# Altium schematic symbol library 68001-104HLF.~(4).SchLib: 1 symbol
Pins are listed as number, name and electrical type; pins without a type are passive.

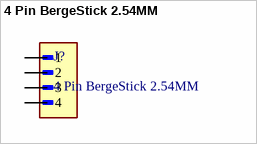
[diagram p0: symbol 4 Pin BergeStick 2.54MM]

## 4 Pin BergeStick 2.54MM
designator J?
4 Pin 4Pos THT BergeStick 2.54MM Amphenol 68001-104HLF 3A
footprint AMPHENOL_68001-104HLF
pins: 1, 2, 3, 4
